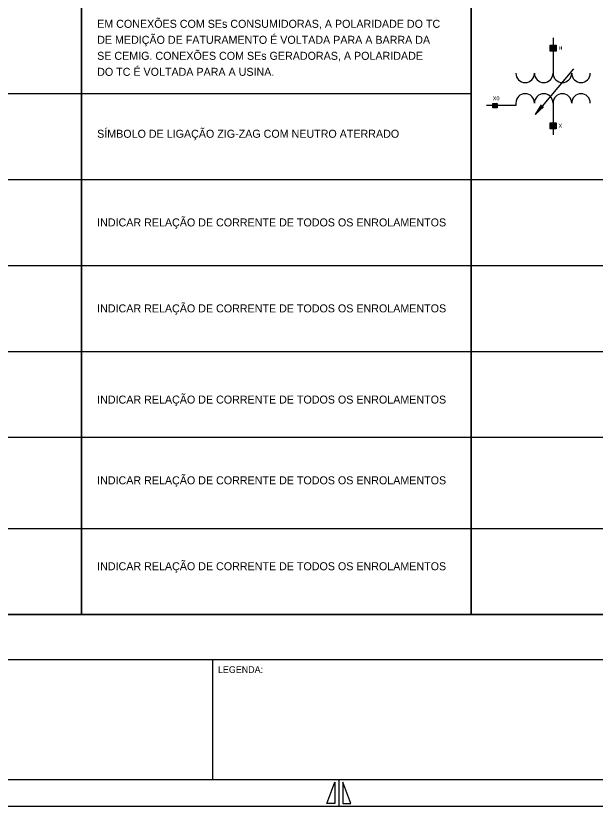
# Model space of a CAD drawing. Extents: x 563 to 3226, y 358 to 960.
# Drawn here: x 782.4 to 999.7, y 358 to 654.3 of the extents above; entities that cross this region are included whole.
import ezdxf

# ---------------------------------------------------------------- set-up
doc = ezdxf.new("R2010")
doc.units = 0
for name, color, linetype in [('COMENTÁRIOS_CEMIG_03-12-2019', 7, 'Continuous'), ('Default', 7, 'Continuous'), ('New Level (0)', 7, 'Continuous')]:
    doc.layers.add(name, color=color, linetype=linetype)

msp = doc.modelspace()

# ---------------------------------------------------------------- linework, layer by layer
at = {"layer": 'COMENTÁRIOS_CEMIG_03-12-2019'}
for p, q in [((982.78, 641.13), (984.93, 643.29)), ((982.78, 641.31), (984.75, 643.29)), ((982.78, 641.49), (984.57, 643.29)), ((982.78, 641.66), (984.4, 643.29)), ((982.78, 641.84), (984.22, 643.29)), ((982.78, 642.02), (984.04, 643.29)), ((982.78, 642.19), (983.87, 643.29)), ((982.78, 642.37), (983.69, 643.29)), ((982.78, 642.55), (983.51, 643.29)), ((982.78, 642.72), (983.34, 643.29)), ((982.78, 642.9), (983.16, 643.29)), ((982.78, 643.08), (982.98, 643.29)), ((982.78, 643.25), (982.81, 643.29)), ((982.89, 641.07), (984.99, 643.17)), ((983.07, 641.07), (984.99, 642.99)), ((983.25, 641.07), (984.99, 642.81)), ((983.42, 641.07), (984.99, 642.64)), ((983.6, 641.07), (984.99, 642.46)), ((983.78, 641.07), (984.99, 642.28)), ((983.95, 641.07), (984.99, 642.11)), ((984.13, 641.07), (984.99, 641.93)), ((984.31, 641.07), (984.99, 641.75)), ((984.49, 641.07), (984.99, 641.58)), ((984.66, 641.07), (984.99, 641.4)), ((984.84, 641.07), (984.99, 641.22)), ((982.78, 612.01), (984.93, 614.17)), ((982.78, 612.19), (984.75, 614.17)), ((982.78, 612.37), (984.57, 614.17)), ((982.78, 612.54), (984.4, 614.17)), ((982.78, 612.72), (984.22, 614.17)), ((982.78, 612.9), (984.04, 614.17)), ((982.78, 613.07), (983.87, 614.17)), ((982.78, 613.25), (983.69, 614.17)), ((982.78, 613.43), (983.51, 614.17)), ((982.78, 613.6), (983.34, 614.17)), ((982.78, 613.78), (983.16, 614.17)), ((982.78, 613.96), (982.98, 614.17)), ((982.78, 614.13), (982.81, 614.17)), ((982.89, 611.95), (984.99, 614.05)), ((983.07, 611.95), (984.99, 613.87)), ((983.25, 611.95), (984.99, 613.69)), ((983.42, 611.95), (984.99, 613.52)), ((983.6, 611.95), (984.99, 613.34)), ((983.78, 611.95), (984.99, 613.16)), ((983.95, 611.95), (984.99, 612.99)), ((984.13, 611.95), (984.99, 612.81)), ((984.31, 611.95), (984.99, 612.63)), ((984.49, 611.95), (984.99, 612.46)), ((984.66, 611.95), (984.99, 612.28)), ((984.84, 611.95), (984.99, 612.1))]:
    msp.add_line(p, q, dxfattribs=at)
for points in [[(982.78, 643.29), (984.99, 643.29), (984.99, 641.07), (982.78, 641.07)], [(982.78, 614.17), (984.99, 614.17), (984.99, 611.95), (982.78, 611.95)]]:
    msp.add_lwpolyline(points, close=True, dxfattribs=at)
at = {"layer": 'Default'}
for p, q in [((983.88, 645.97), (983.88, 632.74)), ((991.51, 634.42), (977.18, 617.33)), ((969.92, 620.62), (958.87, 620.62)), ((961.35, 621.4), (962.91, 621.4)), ((961.35, 619.84), (961.35, 621.4)), ((962.79, 619.84), (961.35, 621.28)), ((962.65, 619.84), (961.35, 621.14)), ((962.51, 619.84), (961.35, 621)), ((962.38, 619.84), (961.35, 620.87)), ((962.24, 619.84), (961.35, 620.73)), ((962.1, 619.84), (961.35, 620.59)), ((961.96, 619.84), (961.35, 620.45)), ((961.82, 619.84), (961.35, 620.32)), ((961.69, 619.84), (961.35, 620.18)), ((961.55, 619.84), (961.35, 620.04)), ((961.41, 619.84), (961.35, 619.9)), ((962.91, 619.84), (961.35, 619.84)), ((962.91, 619.86), (961.37, 621.4)), ((962.91, 620), (961.51, 621.4)), ((962.91, 620.14), (961.64, 621.4)), ((962.91, 620.27), (961.78, 621.4)), ((962.91, 620.41), (961.92, 621.4)), ((962.91, 620.55), (962.06, 621.4)), ((962.91, 620.69), (962.19, 621.4)), ((962.91, 620.82), (962.33, 621.4)), ((962.91, 620.96), (962.47, 621.4)), ((962.91, 621.1), (962.61, 621.4)), ((962.91, 621.24), (962.74, 621.4)), ((962.91, 621.37), (962.88, 621.4)), ((962.91, 621.4), (962.91, 619.84)), ((969.92, 621.58), (969.92, 620.62)), ((979.4, 620.94), (977.18, 617.33)), ((977.18, 617.33), (980.34, 620.15)), ((983.88, 621.59), (983.88, 609.72))]:
    msp.add_line(p, q, dxfattribs=at)
for centre, start, end in [((973.41, 632.75), 180, 0), ((980.39, 632.75), 180, 0), ((987.37, 632.75), 180, 0), ((994.35, 632.75), 180, 0), ((973.41, 621.58), 0, 180), ((980.39, 621.58), 0, 180), ((987.37, 621.58), 0, 180), ((994.35, 621.58), 0, 180)]:
    msp.add_arc(centre, 3.49, start, end, dxfattribs=at)
at = {"layer": 'New Level (0)'}
for p, q in [((603.14, 625.16), (953.22, 625.16)), ((603.14, 592.93), (1303.31, 592.93)), ((603.14, 560.7), (1303.31, 560.7)), ((603.14, 528.47), (1303.31, 528.47)), ((603.14, 528.47), (1303.31, 528.47)), ((603.14, 496.25), (1303.31, 496.25)), ((603.14, 462.06), (1303.31, 462.06)), ((603.14, 429.83), (1303.31, 429.83)), ((572.58, 412.96), (1393.58, 412.96)), ((856.24, 412.96), (856.24, 367.96)), ((572.58, 367.96), (1393.58, 367.96)), ((572.58, 367.96), (1393.58, 367.96)), ((903.58, 367.96), (903.58, 357.96)), ((899.08, 358.96), (902.08, 366.96)), ((902.08, 366.96), (902.08, 358.96)), ((905.08, 366.96), (905.08, 358.96)), ((908.08, 358.96), (905.08, 366.96)), ((902.08, 358.96), (899.08, 358.96)), ((905.08, 358.96), (908.08, 358.96)), ((562.58, 357.96), (1403.58, 357.96)), ((562.58, 357.96), (1403.58, 357.96))]:
    msp.add_line(p, q, dxfattribs=at)
for points in [[(603.14, 915.21), (807.1, 915.21), (807.1, 429.83), (603.14, 429.83)], [(807.1, 915.21), (953.22, 915.21), (953.22, 429.83), (807.1, 429.83)], [(953.22, 915.21), (1157.18, 915.21), (1157.18, 429.83), (953.22, 429.83)]]:
    msp.add_lwpolyline(points, close=True, dxfattribs=at)

# ---------------------------------------------------------------- texts
at = {"layer": 'Default'}
for s, height, p in [('EM CONEXÕES COM SEs CONSUMIDORAS, A POLARIDADE DO TC ', 3, (812.95, 649.78)), ('DE MEDIÇÃO DE FATURAMENTO É VOLTADA PARA A BARRA DA ', 3, (812.95, 643.78)), ('SE CEMIG. CONEXÕES COM SEs GERADORAS, A POLARIDADE ', 3, (812.95, 637.78)), ('H', 1.5, (985.91, 641.43)), ('DO TC É VOLTADA PARA A USINA.', 3, (812.95, 631.78)), ('X0', 1.5, (961.27, 622.56)), ('X', 1.5, (985.91, 612.31)), ('SÍMBOLO DE LIGAÇÃO ZIG-ZAG COM NEUTRO ATERRADO', 3, (812.95, 608.56)), ('INDICAR RELAÇÃO DE CORRENTE DE TODOS OS ENROLAMENTOS', 3, (812.95, 575.32)), ('INDICAR RELAÇÃO DE CORRENTE DE TODOS OS ENROLAMENTOS', 3, (812.95, 543.09)), ('INDICAR RELAÇÃO DE CORRENTE DE TODOS OS ENROLAMENTOS', 3, (812.95, 508.9)), ('INDICAR RELAÇÃO DE CORRENTE DE TODOS OS ENROLAMENTOS', 3, (812.95, 478.63)), ('INDICAR RELAÇÃO DE CORRENTE DE TODOS OS ENROLAMENTOS', 3, (812.95, 446.41))]:
    msp.add_text(s, height=height, dxfattribs=at).set_placement(p)
at = {"layer": 'New Level (0)'}
msp.add_text('LEGENDA:', height=2.5, dxfattribs=at).set_placement((858.24, 407.91))

doc.saveas('drawing.dxf')
